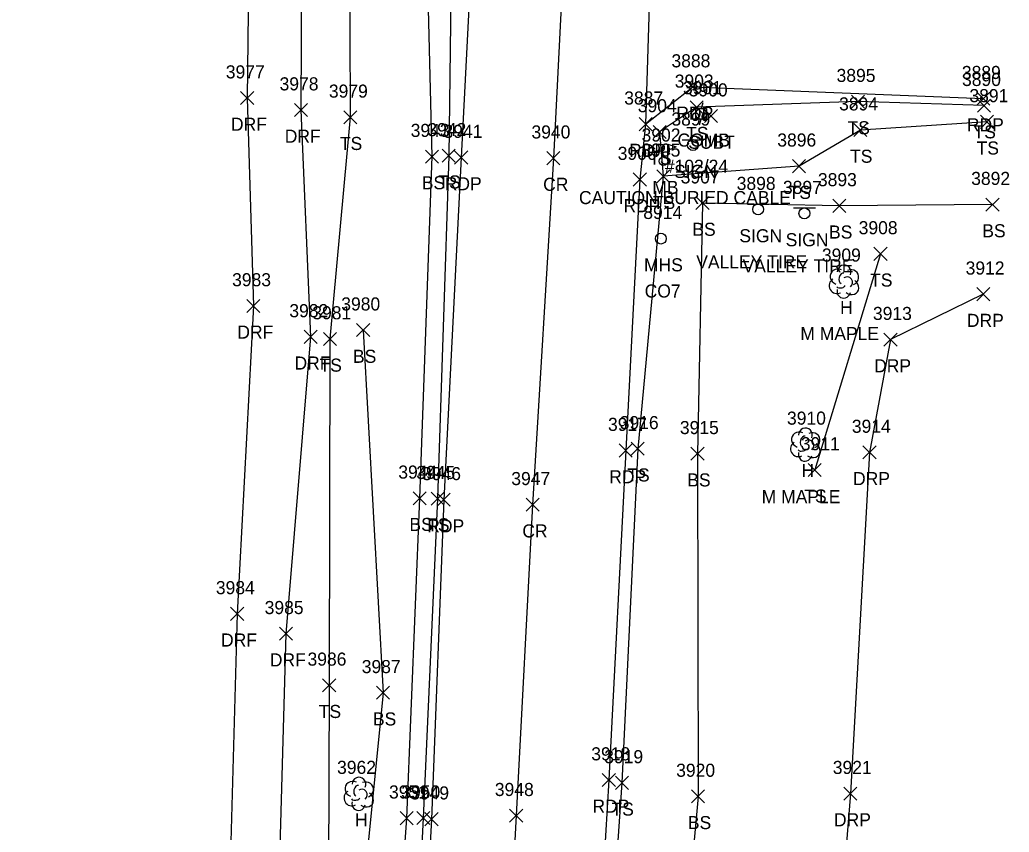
# Model space of a CAD drawing. Extents: x 1678863 to 1683592, y 407783 to 418211.
# Drawn here: x 1680263.1 to 1680414.4, y 413760.9 to 413885.1 of the extents above; entities that cross this region are included whole.
import ezdxf

# ---------------------------------------------------------------- set-up
doc = ezdxf.new("R2010")
doc.units = 0
for name, color, linetype in [('L_A', 7, 'Continuous'), ('L_C', 7, 'Continuous'), ('L_I', 7, 'Continuous'), ('L_TIC', 7, 'Continuous'), ('LELB', 7, 'Continuous'), ('LMB', 7, 'Continuous'), ('LTD', 7, 'Continuous'), ('P_A', 7, 'Continuous'), ('P_I', 7, 'Continuous'), ('P_TIC', 7, 'Continuous'), ('PET', 7, 'Continuous'), ('PRC', 7, 'Continuous'), ('R_A', 7, 'Continuous'), ('R_I', 7, 'Continuous'), ('R_TIC', 7, 'Continuous'), ('RDF', 7, 'Continuous'), ('RDP', 7, 'Continuous'), ('S_A', 7, 'Continuous'), ('S_C', 7, 'Continuous'), ('S_I', 7, 'Continuous'), ('SSGN', 7, 'Continuous'), ('U_A', 7, 'Continuous'), ('U_C', 7, 'Continuous'), ('U_I', 7, 'Continuous'), ('U_TIC', 7, 'Continuous'), ('UP', 7, 'Continuous'), ('USMH', 7, 'Continuous')]:
    doc.layers.add(name, color=color, linetype=linetype)

msp = doc.modelspace()

# ---------------------------------------------------------------- linework, layer by layer
at = {"layer": 'L_TIC'}
for points in [[(1680390.22, 413871.57), (1680392.22, 413873.57)], [(1680392.22, 413871.57), (1680390.22, 413873.57)], [(1680365.56, 413870.7), (1680367.56, 413872.7)], [(1680367.56, 413870.7), (1680365.56, 413872.7)], [(1680409.49, 413870.95), (1680411.49, 413872.95)], [(1680411.49, 413870.95), (1680409.49, 413872.95)], [(1680312.62, 413869.17), (1680314.62, 413871.17)], [(1680314.62, 413869.17), (1680312.62, 413871.17)], [(1680409.96, 413868.48), (1680411.96, 413870.48)], [(1680411.96, 413868.48), (1680409.96, 413870.48)], [(1680390.61, 413867.22), (1680392.61, 413869.22)], [(1680392.61, 413867.22), (1680390.61, 413869.22)], [(1680359.91, 413866.94), (1680361.91, 413868.94)], [(1680361.91, 413866.94), (1680359.91, 413868.94)], [(1680325.11, 413863.17), (1680327.11, 413865.17)], [(1680327.11, 413863.17), (1680325.11, 413865.17)], [(1680327.66, 413863.29), (1680329.66, 413865.29)], [(1680329.66, 413863.29), (1680327.66, 413865.29)], [(1680381.22, 413861.7), (1680383.22, 413863.7)], [(1680383.22, 413861.7), (1680381.22, 413863.7)], [(1680360.47, 413860.16), (1680362.47, 413862.16)], [(1680362.47, 413860.16), (1680360.47, 413862.16)], [(1680360.47, 413860.16), (1680362.47, 413862.16)], [(1680362.47, 413860.16), (1680360.47, 413862.16)], [(1680366.47, 413856.06), (1680368.47, 413858.06)], [(1680368.47, 413856.06), (1680366.47, 413858.06)], [(1680387.37, 413855.64), (1680389.37, 413857.64)], [(1680389.37, 413855.64), (1680387.37, 413857.64)], [(1680410.8, 413855.83), (1680412.8, 413857.83)], [(1680412.8, 413855.83), (1680410.8, 413857.83)], [(1680393.68, 413848.3), (1680395.68, 413850.3)], [(1680395.68, 413848.3), (1680393.68, 413850.3)], [(1680309.5, 413835.3), (1680311.5, 413837.3)], [(1680311.5, 413835.3), (1680309.5, 413837.3)], [(1680314.59, 413836.65), (1680316.59, 413838.65)], [(1680316.59, 413836.65), (1680314.59, 413838.65)], [(1680356.56, 413818.52), (1680358.56, 413820.52)], [(1680358.56, 413818.52), (1680356.56, 413820.52)], [(1680365.7, 413817.76), (1680367.7, 413819.76)], [(1680367.7, 413817.76), (1680365.7, 413819.76)], [(1680383.62, 413815.29), (1680385.62, 413817.29)], [(1680385.62, 413815.29), (1680383.62, 413817.29)], [(1680323.22, 413810.96), (1680325.22, 413812.96)], [(1680325.22, 413810.96), (1680323.22, 413812.96)], [(1680325.97, 413810.9), (1680327.97, 413812.9)], [(1680327.97, 413810.9), (1680325.97, 413812.9)], [(1680309.39, 413782.38), (1680311.39, 413784.38)], [(1680311.39, 413782.38), (1680309.39, 413784.38)], [(1680317.63, 413781.24), (1680319.63, 413783.24)], [(1680319.63, 413781.24), (1680317.63, 413783.24)], [(1680354.15, 413767.47), (1680356.15, 413769.47)], [(1680356.15, 413767.47), (1680354.15, 413769.47)], [(1680365.79, 413765.4), (1680367.79, 413767.4)], [(1680367.79, 413765.4), (1680365.79, 413767.4)], [(1680321.23, 413762.08), (1680323.23, 413764.08)], [(1680323.23, 413762.08), (1680321.23, 413764.08)], [(1680323.77, 413762.09), (1680325.77, 413764.09)], [(1680325.77, 413762.09), (1680323.77, 413764.09)]]:
    msp.add_lwpolyline(points, dxfattribs=at)
at = {"layer": 'LELB'}
for points in [[(1680328.8, 414196.16), (1680329.42, 414154.35), (1680329.9, 414108.73), (1680324.37, 414065.09), (1680323.69, 414045.18), (1680321.93, 414011.62), (1680327.59, 413969.26), (1680329.3, 413913), (1680328.66, 413864.29), (1680326.97, 413811.9), (1680324.77, 413763.09), (1680322.28, 413714.15), (1680319.32, 413666.59), (1680317.19, 413631.47), (1680315.04, 413584.83), (1680311.9, 413541.88), (1680311.77, 413525.72)], [(1680333.49, 414185.64), (1680335.28, 414154.34), (1680335.31, 414108.58), (1680333.17, 414064.14), (1680332.9, 414010.98), (1680327.01, 414005.42), (1680327.59, 413969.26), (1680324.87, 413913.45), (1680326.11, 413864.17), (1680324.22, 413811.96), (1680322.23, 413763.08), (1680318.76, 413714.44), (1680316.65, 413667.05), (1680314.69, 413647.98), (1680313.33, 413619.55), (1680312.59, 413608.22), (1680310.92, 413608.34)], [(1680310.3, 413964.45), (1680313.38, 413925.26), (1680313.62, 413870.17), (1680310.5, 413836.3), (1680310.39, 413783.38), (1680310.23, 413740.98), (1680305.9, 413695.45), (1680302.22, 413648.42), (1680299.26, 413611.53), (1680297.37, 413601.66), (1680307.54, 413597.2), (1680308.18, 413584.58), (1680306.18, 413542.36), (1680304.07, 413518.67), (1680292.7, 413506.12)], [(1680410.49, 413871.95), (1680391.22, 413872.57), (1680366.56, 413871.7), (1680360.91, 413867.94), (1680361.47, 413861.16), (1680357.56, 413819.52), (1680355.15, 413768.47), (1680351.69, 413718.23), (1680349.1, 413665.12), (1680348.01, 413633.93), (1680345.49, 413592.28), (1680344.55, 413583.78), (1680350.55, 413572.29), (1680354.65, 413565.16)], [(1680410.96, 413869.48), (1680391.61, 413868.22), (1680382.22, 413862.7), (1680361.47, 413861.16)], [(1680411.8, 413856.83), (1680388.37, 413856.64), (1680367.47, 413857.06), (1680366.7, 413818.76), (1680366.79, 413766.4), (1680362.43, 413718.53), (1680362.65, 413664.2), (1680360.05, 413633.04), (1680379.39, 413591.61)], [(1680394.68, 413849.3), (1680384.62, 413816.29)], [(1680315.59, 413837.65), (1680318.63, 413782.24), (1680314.59, 413741.41), (1680314.5, 413693.28), (1680312.26, 413647.66), (1680311.86, 413619.89), (1680310.92, 413608.34)]]:
    msp.add_lwpolyline(points, dxfattribs=at)
at = {"layer": 'LMB'}
for p, q in [((1680362.14, 413866.06), (1680363.43, 413865.68)), ((1680362.14, 413863.47), (1680362.14, 413866.06)), ((1680362.14, 413865.16), (1680363.42, 413865.67)), ((1680361.49, 413863.46), (1680361.49, 413863.46))]:
    msp.add_line(p, q, dxfattribs=at)
msp.add_circle((1680361.49, 413863.46), 0.656, dxfattribs=at)
at = {"layer": 'LTD'}
for p, q in [((1680389.07, 413845.12), (1680389.07, 413845.12)), ((1680389.07, 413845.12), (1680389.07, 413845.12)), ((1680383.16, 413820.2), (1680383.16, 413820.2)), ((1680383.16, 413820.2), (1680383.16, 413820.2)), ((1680314.9, 413766.84), (1680314.9, 413766.84)), ((1680314.9, 413766.84), (1680314.9, 413766.84))]:
    msp.add_line(p, q, dxfattribs=at)
for centre in [(1680389.12, 413846.55), (1680383.2, 413821.64), (1680314.95, 413768.27)]:
    msp.add_arc(centre, 1.05, 335.5272, 180.9563, dxfattribs=at)
for centre, major_axis, ratio, start_param, end_param in [((1680388.28, 413845.78), (1.21, -0.51), 0.895232, 1.570796, 4.712389), ((1680388.86, 413845.58), (-0.208, -0.792), 0.645439, 3.141593, 6.283185), ((1680390.11, 413845.7), (-1.14, -0.48), 0.949671, 1.570796, 4.712389), ((1680387.99, 413844.41), (0.58, -1.04), 0.959034, 3.141593, 6.283185), ((1680389.57, 413844.95), (-0.5, 0.667), 0.989748, 3.141593, 6.283185), ((1680390.07, 413844.29), (-1.09, 0.79), 0.841452, 1.570796, 4.712389), ((1680389.07, 413843.62), (0.26, 1.06), 0.942809, 1.570796, 4.712389), ((1680388.61, 413844.37), (-0.625, -0.083), 0.423636, 0, 3.141593), ((1680382.37, 413820.87), (1.21, -0.51), 0.895232, 1.570796, 4.712389), ((1680384.2, 413820.79), (-1.14, -0.48), 0.949671, 1.570796, 4.712389), ((1680382.95, 413820.66), (-0.208, -0.792), 0.645439, 3.141593, 6.283185), ((1680383.66, 413820.04), (-0.5, 0.667), 0.989748, 3.141593, 6.283185), ((1680382.07, 413819.49), (0.58, -1.04), 0.959034, 3.141593, 6.283185), ((1680382.7, 413819.45), (-0.625, -0.083), 0.423636, 0, 3.141593), ((1680384.16, 413819.37), (-1.09, 0.79), 0.841452, 1.570796, 4.712389), ((1680383.16, 413818.7), (0.26, 1.06), 0.942809, 1.570796, 4.712389), ((1680314.11, 413767.5), (1.21, -0.51), 0.895232, 1.570796, 4.712389), ((1680314.69, 413767.29), (-0.208, -0.792), 0.645439, 3.141593, 6.283185), ((1680315.94, 413767.42), (-1.14, -0.48), 0.949671, 1.570796, 4.712389), ((1680313.82, 413766.13), (0.58, -1.04), 0.959034, 3.141593, 6.283185), ((1680314.44, 413766.09), (-0.625, -0.083), 0.423636, 0, 3.141593), ((1680315.4, 413766.67), (-0.5, 0.667), 0.989748, 3.141593, 6.283185), ((1680315.9, 413766), (-1.09, 0.79), 0.841452, 1.570796, 4.712389), ((1680314.9, 413765.34), (0.26, 1.06), 0.942809, 1.570796, 4.712389)]:
    msp.add_ellipse(centre, major_axis=major_axis, ratio=ratio, start_param=start_param, end_param=end_param, dxfattribs=at)
at = {"layer": 'P_TIC'}
for points in [[(1680364.98, 413873.8), (1680366.98, 413875.8)], [(1680366.98, 413873.8), (1680364.98, 413875.8)], [(1680409.39, 413872.02), (1680411.39, 413874.02)], [(1680411.39, 413872.02), (1680409.39, 413874.02)], [(1680357.76, 413868.12), (1680359.76, 413870.12)], [(1680359.76, 413868.12), (1680357.76, 413870.12)], [(1680357.76, 413868.12), (1680359.76, 413870.12)], [(1680359.76, 413868.12), (1680357.76, 413870.12)], [(1680329.57, 413863.02), (1680331.57, 413865.02)], [(1680331.57, 413863.02), (1680329.57, 413865.02)], [(1680343.67, 413862.93), (1680345.67, 413864.93)], [(1680345.67, 413862.93), (1680343.67, 413864.93)], [(1680356.89, 413859.66), (1680358.89, 413861.66)], [(1680358.89, 413859.66), (1680356.89, 413861.66)], [(1680354.72, 413818.25), (1680356.72, 413820.25)], [(1680356.72, 413818.25), (1680354.72, 413820.25)], [(1680326.9, 413810.73), (1680328.9, 413812.73)], [(1680328.9, 413810.73), (1680326.9, 413812.73)], [(1680340.49, 413809.97), (1680342.49, 413811.97)], [(1680342.49, 413809.97), (1680340.49, 413811.97)], [(1680352.15, 413767.91), (1680354.15, 413769.91)], [(1680354.15, 413767.91), (1680352.15, 413769.91)], [(1680325.03, 413761.93), (1680327.03, 413763.93)], [(1680327.03, 413761.93), (1680325.03, 413763.93)], [(1680337.98, 413762.46), (1680339.98, 413764.46)], [(1680339.98, 413762.46), (1680337.98, 413764.46)]]:
    msp.add_lwpolyline(points, dxfattribs=at)
at = {"layer": 'PET'}
for points in [[(1680337.74, 414063.85), (1680336.89, 414010.83), (1680335.53, 413968.42), (1680333.05, 413912.65), (1680330.57, 413864.02), (1680327.9, 413811.73), (1680326.03, 413762.93), (1680323.35, 413714.16), (1680320.37, 413666.45), (1680318.55, 413631.25), (1680316.14, 413584.69), (1680313.68, 413541.42), (1680312.42, 413523.36), (1680310.1, 413497.18), (1680310.27, 413479.23), (1680309.45, 413465.43), (1680306.28, 413414.4), (1680304.56, 413390.73), (1680303.5, 413367.03), (1680300.17, 413323.12), (1680296.71, 413266.44), (1680294.23, 413226.16), (1680292.89, 413196.25), (1680291.23, 413147.08)], [(1680365.04, 414025.12), (1680363.57, 413992.05), (1680361.98, 413945.68), (1680359.55, 413895.48), (1680358.76, 413869.12), (1680357.89, 413860.66), (1680355.72, 413819.25), (1680353.15, 413768.91), (1680350.09, 413717.59), (1680347.28, 413665.47), (1680345.99, 413633.9), (1680343.8, 413592.27), (1680342.77, 413574.68), (1680340.07, 413539.43), (1680339.13, 413515.37), (1680337.39, 413483.26), (1680333.74, 413422.22), (1680332.43, 413393.84), (1680331.39, 413363.68), (1680328.51, 413328.7), (1680325.07, 413264.49), (1680323.24, 413225.37), (1680321.3, 413184.73)], [(1680358.76, 413869.12), (1680365.98, 413874.8), (1680410.39, 413873.02)]]:
    msp.add_lwpolyline(points, dxfattribs=at)
at = {"layer": 'PRC'}
msp.add_lwpolyline([(1680351.68, 414063.47), (1680351.07, 414011.17), (1680349.92, 413968.85), (1680347.07, 413911.41), (1680344.67, 413863.93), (1680341.49, 413810.97), (1680338.98, 413763.46), (1680336.26, 413713.21), (1680333.88, 413665.73), (1680331.73, 413629.34), (1680329.35, 413585.64), (1680326.79, 413539.67), (1680324.56, 413493.26), (1680322.55, 413462.88), (1680320.16, 413417.83), (1680318.29, 413388.45), (1680316.89, 413365.1), (1680314.19, 413322.55), (1680311.04, 413264.13), (1680308.9, 413226.32), (1680307.27, 413195.54), (1680304.84, 413145.79)], dxfattribs=at)
at = {"layer": 'R_TIC'}
for points in [[(1680296.85, 413872.11), (1680298.85, 413874.11)], [(1680298.85, 413872.11), (1680296.85, 413874.11)], [(1680305.07, 413870.28), (1680307.07, 413872.28)], [(1680307.07, 413870.28), (1680305.07, 413872.28)], [(1680409.39, 413842.14), (1680411.39, 413844.14)], [(1680411.39, 413842.14), (1680409.39, 413844.14)], [(1680297.81, 413840.35), (1680299.81, 413842.35)], [(1680299.81, 413840.35), (1680297.81, 413842.35)], [(1680306.56, 413835.62), (1680308.56, 413837.62)], [(1680308.56, 413835.62), (1680306.56, 413837.62)], [(1680395.21, 413835.2), (1680397.21, 413837.2)], [(1680397.21, 413835.2), (1680395.21, 413837.2)], [(1680391.99, 413817.96), (1680393.99, 413819.96)], [(1680393.99, 413817.96), (1680391.99, 413819.96)], [(1680295.33, 413793.3), (1680297.33, 413795.3)], [(1680297.33, 413793.3), (1680295.33, 413795.3)], [(1680302.79, 413790.26), (1680304.79, 413792.26)], [(1680304.79, 413790.26), (1680302.79, 413792.26)], [(1680389.07, 413765.83), (1680391.07, 413767.83)], [(1680391.07, 413765.83), (1680389.07, 413767.83)]]:
    msp.add_lwpolyline(points, dxfattribs=at)
at = {"layer": 'RDF'}
for points in [[(1680293.38, 413994.57), (1680304.05, 413962.38), (1680306.31, 413925.24), (1680306.07, 413871.28), (1680307.56, 413836.62), (1680303.79, 413791.26), (1680302.36, 413740.49), (1680301.95, 413696.62), (1680297.83, 413647.55), (1680295.14, 413608.28), (1680287.08, 413579.47)], [(1680285.71, 413990.78), (1680295.95, 413964.17), (1680298.49, 413925.92), (1680297.85, 413873.11), (1680298.81, 413841.35), (1680296.33, 413794.3), (1680294.84, 413741.14), (1680291.28, 413693.58), (1680288.32, 413644.74), (1680285.28, 413613.34), (1680275.4, 413582.62), (1680263.09, 413554.99)]]:
    msp.add_lwpolyline(points, dxfattribs=at)
at = {"layer": 'RDP'}
msp.add_lwpolyline([(1680410.39, 413843.14), (1680396.21, 413836.2), (1680392.99, 413818.96), (1680390.07, 413766.83), (1680385.93, 413715.47), (1680385.52, 413679.68), (1680392.6, 413679.63)], dxfattribs=at)
at = {"layer": 'SSGN'}
for p, q in [((1680364.35, 413866.75), (1680367.69, 413866.75)), ((1680366, 413865.92), (1680366, 413865.92)), ((1680374.32, 413856.92), (1680377.65, 413856.92)), ((1680375.97, 413856.09), (1680375.97, 413856.09)), ((1680381.39, 413856.31), (1680384.73, 413856.31)), ((1680383.04, 413855.48), (1680383.04, 413855.48))]:
    msp.add_line(p, q, dxfattribs=at)
for centre in [(1680366, 413865.92), (1680375.97, 413856.09), (1680383.04, 413855.48)]:
    msp.add_circle(centre, 0.833, dxfattribs=at)
at = {"layer": 'U_TIC'}
for points in [[(1680367.78, 413869.36), (1680369.78, 413871.36)], [(1680369.78, 413869.36), (1680367.78, 413871.36)]]:
    msp.add_lwpolyline(points, dxfattribs=at)
at = {"layer": 'UP'}
for p, q in [((1680367.5, 413872.36), (1680367.25, 413871.53)), ((1680366.42, 413869.86), (1680366.42, 413871.53)), ((1680366.42, 413871.53), (1680368.08, 413871.53)), ((1680367.25, 413870.69), (1680367.25, 413870.69)), ((1680368.08, 413871.53), (1680368.08, 413869.86)), ((1680368.08, 413869.86), (1680366.42, 413869.86)), ((1680367, 413869.03), (1680367.25, 413869.86))]:
    msp.add_line(p, q, dxfattribs=at)
msp.add_circle((1680367.25, 413870.69), 0.833, dxfattribs=at)
at = {"layer": 'USMH'}
for p, q in [((1680361.1, 413851.63), (1680361.1, 413851.63)), ((1680361.94, 413851.63), (1680361.94, 413851.63))]:
    msp.add_line(p, q, dxfattribs=at)
msp.add_circle((1680361.1, 413851.63), 0.833, dxfattribs=at)

# ---------------------------------------------------------------- texts
at = {"layer": 'L_A'}
for s, p in [('TS', (1680389.63, 413867.57)), ('TS', (1680408.9, 413866.95)), ('TS', (1680364.96, 413866.7)), ('TS', (1680312.03, 413865.17)), ('TS', (1680409.37, 413864.48)), ('TS', (1680359.32, 413862.94)), ('TS', (1680390.02, 413863.22)), ('BS', (1680324.55, 413859.17)), ('TS', (1680327.07, 413859.29)), ('MB', (1680359.79, 413858.46)), ('TS', (1680380.63, 413857.7)), ('TS', (1680359.88, 413856.16)), ('TS', (1680359.88, 413856.16)), ('BS', (1680365.91, 413852.06)), ('BS', (1680410.24, 413851.83)), ('BS', (1680386.81, 413851.64)), ('TS', (1680393.09, 413844.3)), ('H', (1680388.5, 413840.12)), ('BS', (1680314.03, 413832.65)), ('TS', (1680308.91, 413831.3)), ('TS', (1680355.97, 413814.52)), ('H', (1680382.59, 413815.2)), ('BS', (1680365.14, 413813.76)), ('TS', (1680383.03, 413811.29)), ('BS', (1680322.66, 413806.96)), ('TS', (1680325.37, 413806.9)), ('TS', (1680308.8, 413778.38)), ('BS', (1680317.08, 413777.24)), ('TS', (1680353.55, 413763.47)), ('H', (1680314.34, 413761.84)), ('BS', (1680365.23, 413761.4))]:
    msp.add_text(s, height=2, dxfattribs=at).set_placement(p)
at = {"layer": 'L_C'}
for p in [(1680382.42, 413836.12), (1680376.51, 413811.2)]:
    msp.add_text('M MAPLE', height=2, dxfattribs=at).set_placement(p)
at = {"layer": 'L_I'}
for s, p in [('3903', (1680363.22, 413874.7)), ('3895', (1680387.96, 413875.57)), ('3890', (1680407.14, 413874.95)), ('3979', (1680310.35, 413873.17)), ('3891', (1680408.27, 413872.48)), ('3904', (1680357.57, 413870.94)), ('3894', (1680388.35, 413871.22)), ('3943', (1680322.85, 413867.17)), ('3942', (1680325.4, 413867.29)), ('3902', (1680358.15, 413866.46)), ('3896', (1680378.9, 413865.7)), ('3905', (1680358.13, 413864.16)), ('3905', (1680358.13, 413864.16)), ('3907', (1680364.13, 413860.06)), ('3893', (1680385.11, 413859.64)), ('3892', (1680408.54, 413859.83)), ('3908', (1680391.34, 413852.3)), ('3909', (1680385.72, 413848.12)), ('3980', (1680312.24, 413840.65)), ('3981', (1680307.81, 413839.3)), ('3910', (1680380.38, 413823.2)), ('3916', (1680354.81, 413822.52)), ('3915', (1680364.01, 413821.76)), ('3911', (1680382.5, 413819.29)), ('3944', (1680320.96, 413814.96)), ('3945', (1680323.71, 413814.9)), ('3986', (1680307.08, 413786.38)), ('3987', (1680315.37, 413785.24)), ('3919', (1680352.44, 413771.47)), ('3962', (1680311.6, 413769.84)), ('3920', (1680363.44, 413769.4)), ('3951', (1680319.54, 413766.08)), ('3950', (1680321.42, 413766.09))]:
    msp.add_text(s, height=2, dxfattribs=at).set_placement(p)
at = {"layer": 'P_A'}
for s, p in [('RDP', (1680363.47, 413869.8)), ('RDP', (1680407.88, 413868.02)), ('RDP', (1680356.25, 413864.12)), ('RDP', (1680356.25, 413864.12)), ('RDP', (1680328.06, 413859.02)), ('CR', (1680343.1, 413858.93)), ('RDP', (1680355.38, 413855.66)), ('RDP', (1680353.2, 413814.25)), ('RDP', (1680325.39, 413806.73)), ('CR', (1680339.92, 413805.97)), ('RDP', (1680350.64, 413763.91))]:
    msp.add_text(s, height=2, dxfattribs=at).set_placement(p)
at = {"layer": 'P_I'}
for s, p in [('3888', (1680362.72, 413877.8)), ('3889', (1680407.12, 413876.02)), ('3887', (1680355.5, 413872.12)), ('3887', (1680355.5, 413872.12)), ('3941', (1680327.87, 413867.02)), ('3940', (1680341.32, 413866.93)), ('3906', (1680354.5, 413863.66)), ('3917', (1680353.02, 413822.25)), ('3946', (1680324.59, 413814.73)), ('3947', (1680338.23, 413813.97)), ('3918', (1680350.46, 413771.91)), ('3949', (1680322.77, 413765.93)), ('3948', (1680335.72, 413766.46))]:
    msp.add_text(s, height=2, dxfattribs=at).set_placement(p)
at = {"layer": 'R_A'}
for s, p in [('DRF', (1680295.38, 413868.11)), ('DRF', (1680303.6, 413866.28)), ('DRP', (1680407.88, 413838.14)), ('DRF', (1680296.35, 413836.35)), ('DRF', (1680305.09, 413831.62)), ('DRP', (1680393.7, 413831.2)), ('DRP', (1680390.48, 413813.96)), ('DRF', (1680293.86, 413789.3)), ('DRF', (1680301.32, 413786.26)), ('DRP', (1680387.56, 413761.83))]:
    msp.add_text(s, height=2, dxfattribs=at).set_placement(p)
at = {"layer": 'R_I'}
for s, p in [('3977', (1680294.59, 413876.11)), ('3978', (1680302.81, 413874.28)), ('3912', (1680407.69, 413846.14)), ('3983', (1680295.55, 413844.35)), ('3982', (1680304.3, 413839.62)), ('3913', (1680393.52, 413839.2)), ('3914', (1680390.3, 413821.96)), ('3984', (1680293.07, 413797.3)), ('3985', (1680300.53, 413794.26)), ('3921', (1680387.38, 413769.83))]:
    msp.add_text(s, height=2, dxfattribs=at).set_placement(p)
at = {"layer": 'S_A'}
for p in [(1680363.14, 413860.9), (1680373.1, 413851.07), (1680380.18, 413850.46)]:
    msp.add_text('SIGN', height=2, dxfattribs=at).set_placement(p)
at = {"layer": 'S_C'}
for s, p in [('CAUTION BURIED CABLE', (1680348.58, 413856.9)), ('VALLEY TIRE', (1680366.51, 413847.07)), ('VALLEY TIRE', (1680373.59, 413846.46))]:
    msp.add_text(s, height=2, dxfattribs=at).set_placement(p)
at = {"layer": 'S_I'}
for s, p in [('3899', (1680362.71, 413868.9)), ('3898', (1680372.69, 413859.07)), ('3897', (1680379.76, 413858.46))]:
    msp.add_text(s, height=2, dxfattribs=at).set_placement(p)
at = {"layer": 'U_A'}
for s, p in [('COMB', (1680363.64, 413865.69)), ('SUBT', (1680365.28, 413865.36)), ('MHS', (1680358.52, 413846.63))]:
    msp.add_text(s, height=2, dxfattribs=at).set_placement(p)
at = {"layer": 'U_C'}
for s, p in [('#102/24', (1680361.71, 413861.69)), ('CO7', (1680358.62, 413842.63))]:
    msp.add_text(s, height=2, dxfattribs=at).set_placement(p)
at = {"layer": 'U_I'}
for s, p in [('3901', (1680364.48, 413873.69)), ('3900', (1680365.36, 413873.36)), ('8914', (1680358.41, 413854.63))]:
    msp.add_text(s, height=2, dxfattribs=at).set_placement(p)

doc.saveas('drawing.dxf')
